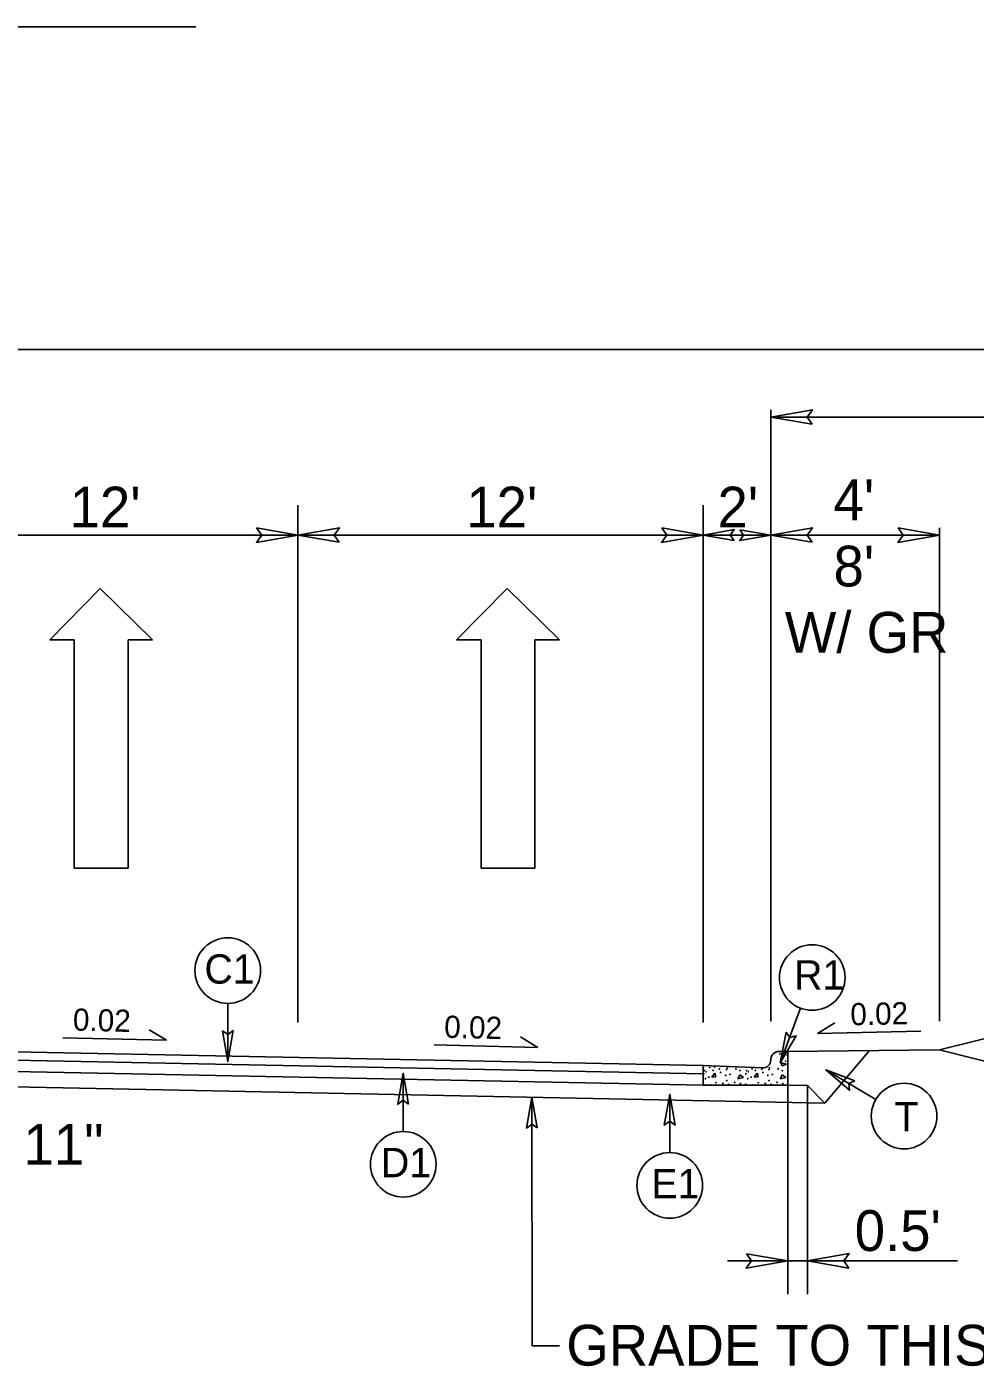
# Model space of a CAD drawing. Extents: x 3025871 to 3026431, y 707165 to 707825.
# Drawn here: x 3026186.78 to 3026214.88, y 707593.8 to 707633.51 of the extents above; entities that cross this region are included whole.
import ezdxf

# ---------------------------------------------------------------- set-up
doc = ezdxf.new("R2010")
doc.units = 0
for name, color, linetype in [('Prop Drainage Structure Junction Box with Manhole CELL', 7, 'Continuous'), ('Prop Drainage Structure Junction Box with Slab Lid TB 840 34 CELL', 7, 'Continuous'), ('Prop Drainage Structure Plot Symbol 50 Scale', 7, 'Continuous'), ('Prop Pavement Schedule Description CELL', 7, 'Continuous'), ('Sheet Data Field CELL', 7, 'Continuous'), ('Sheet Plot Border Inside CELL', 7, 'Continuous'), ('Sheet Sticker Incomplete CELL', 7, 'Continuous'), ('Sheet Typical CELL', 7, 'Continuous'), ('Typical Arrow Superelevation CELL', 7, 'Continuous'), ('Typical Grade Point Symbol CELL', 7, 'Continuous'), ('Typical Text Centerline CELL', 7, 'Continuous'), ('Typical Text Grade Point CELL', 7, 'Continuous')]:
    doc.layers.add(name, color=color, linetype=linetype)

msp = doc.modelspace()

# ---------------------------------------------------------------- linework, layer by layer
at = {"layer": 'Prop Drainage Structure Junction Box with Manhole CELL'}
msp.add_line((3026210.43, 707601.603), (3026180.321, 707602.206), dxfattribs=at)
at = {"layer": 'Prop Drainage Structure Junction Box with Slab Lid TB 840 34 CELL'}
for p, q in [((3026156.341, 707633.51), (3026191.781, 707633.51)), ((3026129.313, 707623.941), (3026223.827, 707623.941)), ((3026208.827, 707604.029), (3026208.827, 707622.159)), ((3026208.827, 707621.941), (3026223.827, 707621.941)), ((3026194.811, 707603.988), (3026194.811, 707619.333)), ((3026206.819, 707603.988), (3026206.819, 707619.333)), ((3026141.303, 707618.441), (3026206.819, 707618.441)), ((3026206.819, 707618.441), (3026208.827, 707618.441)), ((3026208.827, 707618.441), (3026213.827, 707618.441)), ((3026213.827, 707604.029), (3026213.827, 707618.652)), ((3026209.328, 707602.132), (3026209.328, 707595.934)), ((3026209.913, 707602.144), (3026209.913, 707595.934)), ((3026214.361, 707596.924), (3026207.541, 707596.924)), ((3026202.563, 707594.41), (3026201.753, 707594.41))]:
    msp.add_line(p, q, dxfattribs=at)
at = {"layer": 'Prop Drainage Structure Plot Symbol 50 Scale'}
for p, q in [((3026208.826, 707602.885), (3026208.826, 707602.895)), ((3026209.328, 707603.136), (3026209.067, 707603.136)), ((3026209.328, 707602.132), (3026209.328, 707603.136)), ((3026206.819, 707602.132), (3026206.819, 707602.717)), ((3026206.819, 707602.717), (3026208.576, 707602.644)), ((3026207.081, 707602.373), (3026207.167, 707602.493)), ((3026207.167, 707602.493), (3026207.202, 707602.379)), ((3026207.849, 707602.321), (3026207.912, 707602.436)), ((3026207.912, 707602.436), (3026208.015, 707602.361)), ((3026208.335, 707602.373), (3026208.421, 707602.493)), ((3026208.421, 707602.493), (3026208.455, 707602.379)), ((3026209.102, 707602.321), (3026209.165, 707602.436)), ((3026209.137, 707602.801), (3026209.153, 707602.71)), ((3026209.291, 707602.756), (3026209.137, 707602.801)), ((3026209.153, 707602.71), (3026209.291, 707602.756)), ((3026209.165, 707602.436), (3026209.268, 707602.361)), ((3026209.328, 707602.132), (3026206.819, 707602.132)), ((3026207.202, 707602.379), (3026207.081, 707602.373)), ((3026208.015, 707602.361), (3026207.849, 707602.321)), ((3026208.455, 707602.379), (3026208.335, 707602.373)), ((3026209.268, 707602.361), (3026209.102, 707602.321))]:
    msp.add_line(p, q, dxfattribs=at)
for centre in [(3026209.097, 707603.06), (3026209.263, 707602.842), (3026209.315, 707603.025), (3026206.836, 707602.47), (3026206.853, 707602.568), (3026206.909, 707602.533), (3026207.018, 707602.659), (3026207.115, 707602.573), (3026207.161, 707602.676), (3026207.31, 707602.613), (3026207.339, 707602.511), (3026207.488, 707602.425), (3026207.517, 707602.597), (3026207.534, 707602.647), (3026207.614, 707602.453), (3026207.792, 707602.619), (3026207.912, 707602.568), (3026208.09, 707602.47), (3026208.107, 707602.568), (3026208.163, 707602.533), (3026208.272, 707602.616), (3026208.369, 707602.573), (3026208.564, 707602.613), (3026208.593, 707602.511), (3026208.742, 707602.425), (3026208.77, 707602.597), (3026208.787, 707602.647), (3026208.868, 707602.453), (3026209.045, 707602.619), (3026209.166, 707602.568), (3026206.83, 707602.161), (3026206.893, 707602.327), (3026206.99, 707602.373), (3026207.041, 707602.138), (3026207.201, 707602.207), (3026207.408, 707602.184), (3026207.522, 707602.27), (3026207.58, 707602.155), (3026207.757, 707602.218), (3026207.929, 707602.178), (3026208.084, 707602.161), (3026208.147, 707602.327), (3026208.243, 707602.373), (3026208.295, 707602.138), (3026208.455, 707602.207), (3026208.661, 707602.184), (3026208.776, 707602.27), (3026208.833, 707602.155), (3026209.011, 707602.218), (3026209.183, 707602.178)]:
    msp.add_circle(centre, 0.00805, dxfattribs=at)
for centre, start, end in [((3026208.586, 707602.885), 267.6155, 0), ((3026209.067, 707602.895), 90, 180)]:
    msp.add_arc(centre, 0.24, start, end, dxfattribs=at)
at = {"layer": 'Prop Pavement Schedule Description CELL'}
for p, q in [((3026206.819, 707602.717), (3026182.811, 707603.198)), ((3026182.811, 707602.948), (3026206.819, 707602.467)), ((3026206.819, 707602.134), (3026182.814, 707602.614))]:
    msp.add_line(p, q, dxfattribs=at)
at = {"layer": 'Sheet Data Field CELL'}
for p, q in [((3026187.454, 707615.338), (3026188.953, 707616.862)), ((3026188.953, 707616.862), (3026190.5, 707615.338)), ((3026199.513, 707615.338), (3026201.012, 707616.862)), ((3026201.012, 707616.862), (3026202.559, 707615.338)), ((3026188.179, 707615.338), (3026187.454, 707615.338)), ((3026188.179, 707608.568), (3026188.179, 707615.338)), ((3026190.5, 707615.338), (3026189.775, 707615.338)), ((3026189.775, 707615.338), (3026189.775, 707608.568)), ((3026200.238, 707615.338), (3026199.513, 707615.338)), ((3026200.238, 707608.568), (3026200.238, 707615.338)), ((3026202.559, 707615.338), (3026201.834, 707615.338)), ((3026201.834, 707615.338), (3026201.834, 707608.568)), ((3026189.775, 707608.568), (3026188.179, 707608.568)), ((3026201.834, 707608.568), (3026200.238, 707608.568))]:
    msp.add_line(p, q, dxfattribs=at)
at = {"layer": 'Sheet Plot Border Inside CELL'}
msp.add_line((3026209.913, 707602.12), (3026209.328, 707602.132), dxfattribs=at)
at = {"layer": 'Sheet Sticker Incomplete CELL'}
for p, q in [((3026190.914, 707603.465), (3026190.4, 707603.779)), ((3026210.209, 707603.67), (3026210.725, 707603.982)), ((3026210.209, 707603.67), (3026213.277, 707603.732)), ((3026190.914, 707603.465), (3026187.846, 707603.542)), ((3026201.918, 707603.254), (3026198.851, 707603.33)), ((3026201.918, 707603.254), (3026201.404, 707603.568))]:
    msp.add_line(p, q, dxfattribs=at)
at = {"layer": 'Sheet Typical CELL'}
for p, q in [((3026209.328, 707603.136), (3026213.827, 707603.18)), ((3026210.43, 707601.603), (3026211.753, 707603.159)), ((3026209.913, 707602.12), (3026210.43, 707601.603))]:
    msp.add_line(p, q, dxfattribs=at)
at = {"layer": 'Typical Grade Point Symbol CELL'}
for p, q in [((3026192.733, 707602.835), (3026192.732, 707604.559)), ((3026209.105, 707602.801), (3026209.711, 707604.415)), ((3026197.934, 707600.76), (3026197.933, 707602.485)), ((3026211.939, 707601.712), (3026210.454, 707602.588)), ((3026201.753, 707594.41), (3026201.748, 707601.777)), ((3026205.832, 707600.135), (3026205.831, 707601.86))]:
    msp.add_line(p, q, dxfattribs=at)
for centre in [(3026192.732, 707605.531), (3026210.054, 707605.325), (3026212.776, 707601.217), (3026197.934, 707599.788), (3026205.832, 707599.163)]:
    msp.add_circle(centre, 0.972, dxfattribs=at)
at = {"layer": 'Typical Text Centerline CELL'}
for points in [[(3026210.052, 707621.73), (3026208.827, 707621.941), (3026210.059, 707622.159), (3026209.903, 707621.941)], [(3026193.587, 707618.652), (3026194.812, 707618.441), (3026193.58, 707618.223), (3026193.737, 707618.441)], [(3026196.036, 707618.23), (3026194.811, 707618.441), (3026196.043, 707618.659), (3026195.887, 707618.441)], [(3026205.595, 707618.652), (3026206.82, 707618.441), (3026205.588, 707618.223), (3026205.745, 707618.441)], [(3026207.738, 707618.283), (3026206.819, 707618.441), (3026207.743, 707618.604), (3026207.626, 707618.441)], [(3026207.909, 707618.599), (3026208.828, 707618.441), (3026207.904, 707618.278), (3026208.022, 707618.441)], [(3026210.052, 707618.23), (3026208.827, 707618.441), (3026210.059, 707618.659), (3026209.903, 707618.441)], [(3026212.602, 707618.652), (3026213.827, 707618.441), (3026212.595, 707618.223), (3026212.752, 707618.441)], [(3026192.576, 707603.744), (3026192.733, 707602.835), (3026192.894, 707603.75), (3026192.732, 707603.633)], [(3026209.278, 707603.707), (3026209.105, 707602.801), (3026209.578, 707603.6), (3026209.386, 707603.548)], [(3026198.09, 707601.575), (3026197.933, 707602.485), (3026197.772, 707601.57), (3026197.933, 707601.686)], [(3026211.317, 707602.261), (3026210.454, 707602.588), (3026211.159, 707601.984), (3026211.141, 707602.182)], [(3026201.905, 707600.868), (3026201.748, 707601.777), (3026201.587, 707600.862), (3026201.749, 707600.979)], [(3026205.988, 707600.95), (3026205.831, 707601.86), (3026205.669, 707600.945), (3026205.831, 707601.062)], [(3026208.104, 707597.135), (3026209.329, 707596.924), (3026208.097, 707596.706), (3026208.253, 707596.924)], [(3026211.138, 707596.713), (3026209.913, 707596.924), (3026211.145, 707597.142), (3026210.988, 707596.924)]]:
    msp.add_lwpolyline(points, close=True, dxfattribs=at)
at = {"layer": 'Typical Text Grade Point CELL'}
for p, q in [((3026226.993, 707606.471), (3026213.827, 707603.18)), ((3026213.827, 707603.18), (3026226.993, 707599.889))]:
    msp.add_line(p, q, dxfattribs=at)

# ---------------------------------------------------------------- texts
at = {"layer": 'Prop Drainage Structure Junction Box with Slab Lid TB 840 34 CELL'}
for s, height, p in [("12'", 1.2089, (3026188.044, 707618.667)), ("12'", 1.2089, (3026199.801, 707618.667)), ("2'", 1.2089, (3026207.247, 707618.667)), ("4'", 1.2089, (3026210.685, 707618.883)), ("8'", 1.2089, (3026210.685, 707616.918)), ('W/ GR', 1.2089, (3026209.242, 707614.954)), ('11"', 1.2089, (3026186.679, 707599.776)), ("0.5'", 1.2089, (3026211.313, 707597.219)), ('GRADE TO THIS LINE', 1.20892, (3026202.765, 707593.82))]:
    msp.add_text(s, height=height, dxfattribs=at).set_placement(p)
at = {"layer": 'Sheet Sticker Incomplete CELL'}
for s, rotation, p in [('0.02', 358.5679, (3026188.136, 707603.752)), ('0.02 ', 1.2029, (3026211.19, 707603.906)), ('0.02', 358.5679, (3026199.14, 707603.541))]:
    msp.add_text(s, height=0.6583, rotation=rotation, dxfattribs=at).set_placement(p)
at = {"layer": 'Typical Arrow Superelevation CELL'}
for s, p in [('C1', (3026192.04, 707605.143)), ('D1', (3026197.271, 707599.405)), ('E1', (3026205.286, 707598.78))]:
    msp.add_text(s, height=0.87, dxfattribs=at).set_placement(p)
for s, p in [('R1', (3026209.516, 707604.967)), ('T', (3026212.492, 707600.766))]:
    msp.add_text(s, height=0.87, rotation=360, dxfattribs=at).set_placement(p)

doc.saveas('drawing.dxf')
